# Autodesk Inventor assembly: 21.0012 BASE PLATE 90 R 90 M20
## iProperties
Created: 2009-01
Part Number: 21.0012 BASE PLATE 90 R 90 M20
Document SubType Name: Assembly
Designer: Administrator
Author: Administrator
